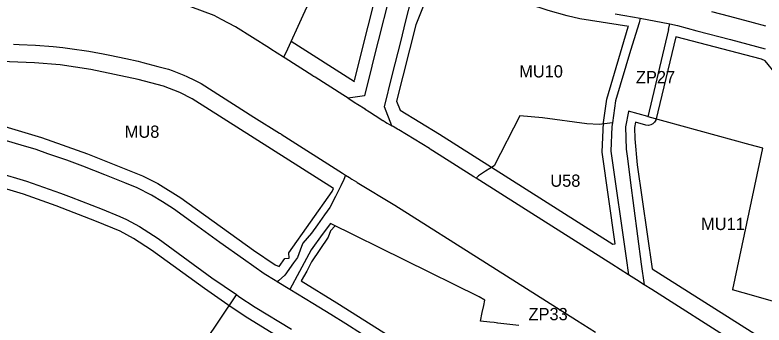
# Model space of a CAD drawing. Extents: x 7428080 to 7432143, y 5545880 to 5549217.
# Drawn here: x 7430217.3 to 7430556.7, y 5547442.4 to 5547582.8 of the extents above; entities that cross this region are included whole.
import ezdxf

# ---------------------------------------------------------------- set-up
doc = ezdxf.new("R2010")
doc.units = 0
for name, color, linetype in [('CZ_L_linie rozgraniczające tereny o różnym przeznaczeniu oraz różnych warunkach ich zabudowy i zagospodarowania', 7, 'Continuous'), ('CZ_L_maksymalne nieprzekraczalne linie zabudowy', 7, 'Continuous'), ('CZ_L_opisy_linie rozgraniczające tereny o różnym przeznaczeniu oraz różnych warunkach ich zabudowy i zagospodarowania', 7, 'Continuous')]:
    doc.layers.add(name, color=color, linetype=linetype)

msp = doc.modelspace()

# ---------------------------------------------------------------- linework, layer by layer
at = {"layer": 'CZ_L_linie rozgraniczające tereny o różnym przeznaczeniu oraz różnych warunkach ich zabudowy i zagospodarowania'}
for p, q in [((7430355.34, 5547599.3), (7430347.7, 5547582.51)), ((7430388.75, 5547598.35), (7430381.91, 5547571.1)), ((7430394.32, 5547579.46), (7430398.17, 5547594.79)), ((7430307.53, 5547582.53), (7430296.98, 5547586.48)), ((7430310.93, 5547580.67), (7430307.53, 5547582.53)), ((7430347.7, 5547582.51), (7430340.03, 5547565.63)), ((7430489.32, 5547583.23), (7430493.65, 5547582.59)), ((7430493.65, 5547582.59), (7430500.62, 5547581.4)), ((7430541.3, 5547582.12), (7430533.09, 5547584.22)), ((7430541.31, 5547582.09), (7430541.3, 5547582.12)), ((7430552.02, 5547579.23), (7430541.31, 5547582.09)), ((7430317.14, 5547577.44), (7430310.93, 5547580.67)), ((7430392.25, 5547571.23), (7430394.32, 5547579.46)), ((7430500.09, 5547579.29), (7430496.28, 5547566.74)), ((7430500.13, 5547579.28), (7430500.09, 5547579.29)), ((7430500.62, 5547581.4), (7430500.13, 5547579.28)), ((7430500.62, 5547581.4), (7430514.1, 5547578.73)), ((7430513.49, 5547576.28), (7430514.1, 5547578.73)), ((7430514.1, 5547578.73), (7430517.56, 5547578.04)), ((7430557.59, 5547577.78), (7430552.02, 5547579.23)), ((7430332.58, 5547567.69), (7430317.14, 5547577.44)), ((7430504.3, 5547536.69), (7430513.54, 5547576.27)), ((7430513.54, 5547576.27), (7430513.49, 5547576.28)), ((7430517.56, 5547578.04), (7430526.31, 5547575.55)), ((7430526.31, 5547575.55), (7430541.51, 5547571.64)), ((7430541.51, 5547571.64), (7430557.25, 5547567.51)), ((7430216.64, 5547569.5), (7430219.19, 5547569.4)), ((7430219.19, 5547569.4), (7430226.56, 5547569.08)), ((7430226.56, 5547569.08), (7430234.59, 5547568.45)), ((7430234.59, 5547568.45), (7430238.97, 5547568.1)), ((7430381.91, 5547571.1), (7430379.82, 5547562.76)), ((7430388.28, 5547555.39), (7430392.25, 5547571.23)), ((7430238.97, 5547568.1), (7430242.16, 5547567.63)), ((7430242.16, 5547567.63), (7430250.72, 5547566.39)), ((7430250.72, 5547566.39), (7430253.13, 5547566.01)), ((7430253.13, 5547566.01), (7430257.18, 5547565.16)), ((7430257.18, 5547565.16), (7430260.24, 5547564.52)), ((7430333.16, 5547567.33), (7430332.58, 5547567.69)), ((7430339.02, 5547563.63), (7430333.16, 5547567.33)), ((7430340.03, 5547565.63), (7430339.02, 5547563.63)), ((7430496.28, 5547566.74), (7430489.35, 5547543.84)), ((7430260.24, 5547564.52), (7430267.44, 5547563.01)), ((7430267.44, 5547563.01), (7430273.13, 5547561.82)), ((7430273.13, 5547561.82), (7430275.18, 5547561.32)), ((7430339.71, 5547563.19), (7430339.02, 5547563.63)), ((7430352.25, 5547555.27), (7430339.71, 5547563.19)), ((7430379.82, 5547562.76), (7430379.03, 5547559.63)), ((7430275.18, 5547561.32), (7430279.68, 5547560.12)), ((7430279.68, 5547560.12), (7430281.96, 5547559.51)), ((7430281.96, 5547559.51), (7430286.87, 5547558.2)), ((7430286.87, 5547558.2), (7430288.47, 5547557.61)), ((7430379.03, 5547559.63), (7430375.64, 5547546.13)), ((7430288.47, 5547557.61), (7430293.85, 5547555.56)), ((7430293.85, 5547555.56), (7430295.21, 5547555)), ((7430295.21, 5547555), (7430298.7, 5547553.24)), ((7430352.61, 5547554.99), (7430352.25, 5547555.27)), ((7430352.8, 5547554.9), (7430352.61, 5547554.99)), ((7430352.96, 5547554.79), (7430352.8, 5547554.9)), ((7430353.26, 5547554.64), (7430352.96, 5547554.79)), ((7430365.91, 5547546.59), (7430353.26, 5547554.64)), ((7430384.72, 5547541.24), (7430388.28, 5547555.39)), ((7430298.7, 5547553.24), (7430301.68, 5547551.68)), ((7430301.68, 5547551.68), (7430325.56, 5547536.58)), ((7430368.24, 5547545.11), (7430365.91, 5547546.59)), ((7430375.64, 5547546.13), (7430368.24, 5547545.11)), ((7430368.24, 5547545.11), (7430369.25, 5547544.46)), ((7430369.25, 5547544.46), (7430371.81, 5547542.84)), ((7430371.81, 5547542.84), (7430372.15, 5547542.62)), ((7430372.15, 5547542.62), (7430372.56, 5547542.36)), ((7430372.56, 5547542.36), (7430375.91, 5547540.22)), ((7430388.13, 5547532.54), (7430384.72, 5547541.24)), ((7430489.35, 5547543.84), (7430488, 5547533.87)), ((7430375.91, 5547540.22), (7430375.97, 5547540.2)), ((7430375.97, 5547540.2), (7430378.01, 5547538.89)), ((7430378.01, 5547538.89), (7430380.54, 5547537.27)), ((7430495.31, 5547539.07), (7430493.98, 5547532.11)), ((7430495.33, 5547539.19), (7430495.31, 5547539.07)), ((7430504.03, 5547536.77), (7430495.33, 5547539.19)), ((7430325.56, 5547536.58), (7430337.19, 5547529.23)), ((7430380.54, 5547537.27), (7430384.05, 5547535.03)), ((7430384.05, 5547535.03), (7430384.18, 5547534.96)), ((7430384.18, 5547534.96), (7430384.98, 5547534.45)), ((7430384.98, 5547534.45), (7430385.19, 5547534.32)), ((7430385.19, 5547534.32), (7430386, 5547533.83)), ((7430446.03, 5547537.12), (7430434.44, 5547514.5)), ((7430456.31, 5547536.18), (7430446.03, 5547537.12)), ((7430476.45, 5547533.53), (7430456.31, 5547536.18)), ((7430504.18, 5547536.64), (7430504.03, 5547536.77)), ((7430504.03, 5547536.77), (7430504.3, 5547536.69)), ((7430550.43, 5547524.02), (7430504.18, 5547536.64)), ((7430386, 5547533.83), (7430388.13, 5547532.54)), ((7430388.65, 5547532.23), (7430388.13, 5547532.54)), ((7430389.82, 5547531.52), (7430388.65, 5547532.23)), ((7430390.61, 5547531.04), (7430389.82, 5547531.52)), ((7430391.17, 5547530.7), (7430390.61, 5547531.04)), ((7430482.04, 5547533.16), (7430476.45, 5547533.53)), ((7430488, 5547533.87), (7430482.04, 5547533.16)), ((7430487.78, 5547532.21), (7430487.37, 5547521.04)), ((7430488, 5547533.87), (7430487.78, 5547532.21)), ((7430493.98, 5547532.11), (7430494.24, 5547522.05)), ((7430220.04, 5547523.9), (7430206.84, 5547527.79)), ((7430337.19, 5547529.23), (7430337.55, 5547529.05)), ((7430337.55, 5547529.05), (7430337.72, 5547528.94)), ((7430337.72, 5547528.94), (7430337.94, 5547528.83)), ((7430337.94, 5547528.83), (7430365.69, 5547511.17)), ((7430405.14, 5547522.25), (7430391.17, 5547530.7)), ((7430226.93, 5547521.82), (7430220.04, 5547523.9)), ((7430232.21, 5547519.97), (7430226.93, 5547521.82)), ((7430405.27, 5547522.15), (7430405.14, 5547522.25)), ((7430405.41, 5547522.08), (7430405.27, 5547522.15)), ((7430409.54, 5547519.46), (7430405.41, 5547522.08)), ((7430487.37, 5547521.04), (7430494.4, 5547471.66)), ((7430494.24, 5547522.05), (7430494.71, 5547518.84)), ((7430550, 5547493.33), (7430556.22, 5547522.44)), ((7430556.22, 5547522.44), (7430550.43, 5547524.02)), ((7430240.72, 5547516.98), (7430232.21, 5547519.97)), ((7430425.25, 5547509.49), (7430409.54, 5547519.46)), ((7430494.71, 5547518.84), (7430496.1, 5547508.12)), ((7430247.99, 5547514.3), (7430240.72, 5547516.98)), ((7430257.92, 5547510.42), (7430247.99, 5547514.3)), ((7430434.44, 5547514.5), (7430430.58, 5547512.03)), ((7430206.19, 5547512.39), (7430222.42, 5547507.51)), ((7430365.69, 5547511.17), (7430367.08, 5547510.29)), ((7430430.58, 5547512.03), (7430427.39, 5547510)), ((7430222.42, 5547507.51), (7430230.13, 5547504.8)), ((7430267.08, 5547506.76), (7430257.92, 5547510.42)), ((7430366.25, 5547508.25), (7430364.98, 5547505.38)), ((7430367.08, 5547510.29), (7430366.25, 5547508.25)), ((7430367.08, 5547510.29), (7430368.86, 5547509.15)), ((7430368.86, 5547509.15), (7430369.23, 5547508.92)), ((7430369.23, 5547508.92), (7430369.38, 5547508.85)), ((7430369.38, 5547508.85), (7430369.52, 5547508.74)), ((7430369.52, 5547508.74), (7430369.95, 5547508.48)), ((7430369.95, 5547508.48), (7430371.97, 5547507.26)), ((7430371.97, 5547507.26), (7430372.42, 5547506.98)), ((7430426.21, 5547508.88), (7430425.25, 5547509.49)), ((7430427.03, 5547509.65), (7430426.21, 5547508.88)), ((7430446.98, 5547495.71), (7430426.21, 5547508.88)), ((7430427.39, 5547510), (7430427.03, 5547509.65)), ((7430496.1, 5547508.12), (7430496.11, 5547508.05)), ((7430496.11, 5547508.05), (7430501.1, 5547469.87)), ((7430230.13, 5547504.8), (7430237.89, 5547502.08)), ((7430272.62, 5547504.48), (7430267.08, 5547506.76)), ((7430279.1, 5547501.17), (7430272.62, 5547504.48)), ((7430364.98, 5547505.38), (7430362.53, 5547500.6)), ((7430372.42, 5547506.98), (7430389.47, 5547496.66)), ((7430237.89, 5547502.08), (7430242.79, 5547500.23)), ((7430284.12, 5547498.15), (7430279.1, 5547501.17)), ((7430362.53, 5547500.6), (7430359.89, 5547495.57)), ((7430242.79, 5547500.23), (7430256.72, 5547494.79)), ((7430289.04, 5547495.06), (7430284.12, 5547498.15)), ((7430256.72, 5547494.79), (7430264.76, 5547491.51)), ((7430298.49, 5547488.19), (7430289.04, 5547495.06)), ((7430359.89, 5547495.57), (7430357.51, 5547492.27)), ((7430389.47, 5547496.66), (7430430.92, 5547470.37)), ((7430487.73, 5547469.96), (7430446.98, 5547495.71)), ((7430264.76, 5547491.51), (7430267.75, 5547490.14)), ((7430267.75, 5547490.14), (7430273.72, 5547486.96)), ((7430357.51, 5547492.27), (7430354.3, 5547487.79)), ((7430542.54, 5547458.43), (7430550, 5547493.33)), ((7430273.72, 5547486.96), (7430282.11, 5547481.56)), ((7430310.1, 5547479.76), (7430298.49, 5547488.19)), ((7430354.3, 5547487.79), (7430351.58, 5547484)), ((7430360.19, 5547488.37), (7430356.55, 5547483.4)), ((7430427.7, 5547455.14), (7430360.19, 5547488.37)), ((7430351.58, 5547484), (7430347.76, 5547479.47)), ((7430356.55, 5547483.4), (7430351.46, 5547476.43)), ((7430282.11, 5547481.56), (7430293.54, 5547473.25)), ((7430320.77, 5547472.16), (7430310.1, 5547479.76)), ((7430347.19, 5547477.95), (7430345.32, 5547472.98)), ((7430347.76, 5547479.47), (7430347.19, 5547477.95)), ((7430293.54, 5547473.25), (7430306.53, 5547463.81)), ((7430351.46, 5547476.43), (7430346.23, 5547466.6)), ((7430330.25, 5547465.61), (7430320.77, 5547472.16)), ((7430343.42, 5547470.49), (7430339.64, 5547465.03)), ((7430345.32, 5547472.98), (7430343.42, 5547470.49)), ((7430430.92, 5547470.37), (7430430.93, 5547470.36)), ((7430430.93, 5547470.36), (7430430.94, 5547470.35)), ((7430430.94, 5547470.35), (7430471.7, 5547444.61)), ((7430487.74, 5547469.95), (7430487.73, 5547469.96)), ((7430487.73, 5547469.96), (7430487.73, 5547469.96)), ((7430495.32, 5547465.15), (7430487.74, 5547469.95)), ((7430494.4, 5547471.66), (7430495.18, 5547466.15)), ((7430501.1, 5547469.87), (7430502.43, 5547460.65)), ((7430346.23, 5547466.6), (7430341.87, 5547458.43)), ((7430306.53, 5547463.81), (7430317.59, 5547456.13)), ((7430335.15, 5547462.5), (7430330.25, 5547465.61)), ((7430339.64, 5547465.03), (7430336.71, 5547462.33)), ((7430495.18, 5547466.15), (7430495.32, 5547465.15)), ((7430498.98, 5547462.83), (7430495.32, 5547465.15)), ((7430336.07, 5547461.94), (7430335.15, 5547462.5)), ((7430336.71, 5547462.33), (7430336.07, 5547461.94)), ((7430341.87, 5547458.43), (7430336.07, 5547461.94)), ((7430502.43, 5547460.65), (7430498.98, 5547462.83)), ((7430505.96, 5547458.41), (7430502.43, 5547460.65)), ((7430352.29, 5547452.12), (7430341.87, 5547458.43)), ((7430580.2, 5547411.38), (7430505.96, 5547458.41)), ((7430542.52, 5547458.36), (7430542.54, 5547458.43)), ((7430552.18, 5547455.64), (7430542.52, 5547458.36)), ((7430317.15, 5547455.65), (7430303.32, 5547434.87)), ((7430317.59, 5547456.13), (7430317.15, 5547455.65)), ((7430317.59, 5547456.13), (7430318.69, 5547455.37)), ((7430317.59, 5547456.13), (7430317.59, 5547456.13)), ((7430318.69, 5547455.37), (7430326.12, 5547450.43)), ((7430430.2, 5547453.7), (7430427.7, 5547455.14)), ((7430429.68, 5547451.22), (7430430.2, 5547453.7)), ((7430562.02, 5547452.69), (7430552.18, 5547455.64)), ((7430326.12, 5547450.43), (7430342.6, 5547440.45)), ((7430360.37, 5547447.18), (7430352.29, 5547452.12)), ((7430429.01, 5547448.05), (7430429.68, 5547451.22)), ((7430367.18, 5547442.88), (7430360.37, 5547447.18)), ((7430428.19, 5547444.19), (7430429.01, 5547448.05)), ((7430374.31, 5547438.38), (7430367.18, 5547442.88)), ((7430432.53, 5547443.68), (7430428.19, 5547444.19)), ((7430434.37, 5547443.47), (7430432.53, 5547443.68)), ((7430435.35, 5547443.35), (7430434.37, 5547443.47)), ((7430435.99, 5547443.28), (7430435.35, 5547443.35)), ((7430436.1, 5547443.27), (7430435.99, 5547443.28)), ((7430445.67, 5547442.14), (7430436.1, 5547443.27)), ((7430471.7, 5547444.61), (7430480.33, 5547439.14))]:
    msp.add_line(p, q, dxfattribs=at)
at = {"layer": 'CZ_L_maksymalne nieprzekraczalne linie zabudowy'}
for points in [[(7430371.2, 5547553.08), (7430420.8, 5547750.74)], [(7430495.47, 5547577.51), (7430473.26, 5547581.04), (7430467.54, 5547582.4), (7430458.91, 5547584.79), (7430450.54, 5547587.54), (7430444.79, 5547589.2), (7430435.85, 5547590.28), (7430426.33, 5547590.6), (7430405.05, 5547593.59), (7430398.88, 5547578.32), (7430390.21, 5547543.77), (7430391.83, 5547539.65), (7430409.68, 5547528.84), (7430488.29, 5547479.07), (7430489.28, 5547479.21), (7430483.39, 5547520.62), (7430484.01, 5547534.06), (7430485.45, 5547544.72), (7430495.24, 5547577.37)], [(7430516.8, 5547572.83), (7430507.68, 5547535.14), (7430507.14, 5547534.25), (7430506.38, 5547533.53), (7430505.47, 5547533.04), (7430504.45, 5547532.79), (7430503.15, 5547532.86), (7430498.44, 5547534.17), (7430497.99, 5547531.78), (7430498.12, 5547526.71), (7430499.25, 5547514.97), (7430506.06, 5547467.82), (7430610.64, 5547401.69), (7430632.86, 5547449.99), (7430632.01, 5547455.96), (7430610.29, 5547487.34), (7430561.88, 5547556.31), (7430557.25, 5547561.99), (7430555.54, 5547562.79), (7430516.81, 5547572.86)], [(7430342.42, 5547570.94), (7430371.17, 5547552.73)], [(7430361.62, 5547504.28), (7430297.58, 5547544.8), (7430292, 5547547.66), (7430284.51, 5547550.55), (7430273.17, 5547553.58), (7430251.6, 5547558.16), (7430237.79, 5547560.17), (7430226.11, 5547561.1), (7430211.02, 5547561.7)], [(7430207.98, 5547533.69), (7430229.24, 5547527.37), (7430250.09, 5547519.92), (7430275.12, 5547509.93), (7430281.96, 5547506.44), (7430292.41, 5547500.02), (7430325.31, 5547476.34), (7430335.21, 5547469.6), (7430337.01, 5547468.9), (7430339.6, 5547472.57), (7430341.46, 5547472.67), (7430341.33, 5547475), (7430361.06, 5547502.8), (7430361.62, 5547504.28)], [(7430503.8, 5547291.55), (7430523.13, 5547319.55), (7430479.33, 5547347.76), (7430459.83, 5547358.75), (7430397.54, 5547398.89), (7430356.88, 5547424.55), (7430322.82, 5547445.42), (7430315.28, 5547450.43), (7430303.09, 5547458.89), (7430279.12, 5547476.32), (7430270.95, 5547481.61), (7430264.96, 5547484.82), (7430254.27, 5547489.3), (7430235.92, 5547496.41), (7430221.07, 5547501.63), (7430203.91, 5547506.8), (7430175.96, 5547514.41), (7430170.84, 5547512.07), (7430160.94, 5547493.84), (7430140.6, 5547459.18), (7430136.14, 5547453.22), (7430119.58, 5547433.04), (7430119.2, 5547422.84)], [(7430362.34, 5547487.37), (7430360.29, 5547485.03), (7430359.24, 5547482.24), (7430351.63, 5547471.03), (7430349.51, 5547466.8), (7430347.01, 5547462.43), (7430363.19, 5547452.48), (7430414.4, 5547420.18), (7430469.87, 5547384.43), (7430478.55, 5547379.17), (7430493.59, 5547370.72), (7430498.77, 5547367.34)]]:
    msp.add_lwpolyline(points, dxfattribs=at)

# ---------------------------------------------------------------- texts
at = {"layer": 'CZ_L_opisy_linie rozgraniczające tereny o różnym przeznaczeniu oraz różnych warunkach ich zabudowy i zagospodarowania'}
for s, p in [('MU10', (7430445.8, 5547554.49)), ('ZP27', (7430498.7, 5547551.87)), ('MU8', (7430267.03, 5547527.17)), ('U58', (7430459.89, 5547504.99)), ('MU11', (7430528.23, 5547485.38)), ('ZP33', (7430450.02, 5547444.56))]:
    msp.add_text(s, height=5.549, dxfattribs=at).set_placement(p)

doc.saveas('drawing.dxf')
